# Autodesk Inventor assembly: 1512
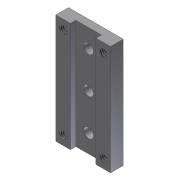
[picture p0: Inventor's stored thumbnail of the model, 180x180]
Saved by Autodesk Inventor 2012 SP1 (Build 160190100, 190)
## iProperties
Created: 2012-02
Part Number: 1512
Document SubType Name: Assembly
Designer: LACO
Author: LACO
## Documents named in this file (3)
- C:\Documents and Settings\LACO\My Documents\Inventor\rainbow-camera-mount\02 parts\1512.iam
- C:\Documents and Settings\LACO\My Documents\Inventor\rainbow-camera-mount\02 parts\1509.ipt
- C:\Documents and Settings\LACO\My Documents\Inventor\rainbow-camera-mount\02 parts\1511.ipt
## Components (3 placed, 2 different names)
1. 1509:1 — Tangent:1, Tangent:2, Tangent:3, Tangent:4, Tangent:5, Tangent:6
2. 1511:1 — Tangent:4, Tangent:5, Tangent:6
3. 1511:2 — Tangent:1, Tangent:2, Tangent:3
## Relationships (6: Tangent 6)
- Tangent:1: 1509:1 ↔ 1511:2
- Tangent:2: 1509:1 ↔ 1511:2
- Tangent:3: 1509:1 ↔ 1511:2
- Tangent:4: 1509:1 ↔ 1511:1
- Tangent:5: 1509:1 ↔ 1511:1
- Tangent:6: 1509:1 ↔ 1511:1
